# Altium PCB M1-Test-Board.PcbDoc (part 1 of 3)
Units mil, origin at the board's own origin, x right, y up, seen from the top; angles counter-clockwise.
Board outline 3977 x 5000 mil, 4 copper layers (Top, GND Layer 2, Power Layer 3, Bottom), stack 60 mil thick; 191 components, 124 nets, 579 pads, 189 vias.
Unrouted connection lines stored in the file: 80.
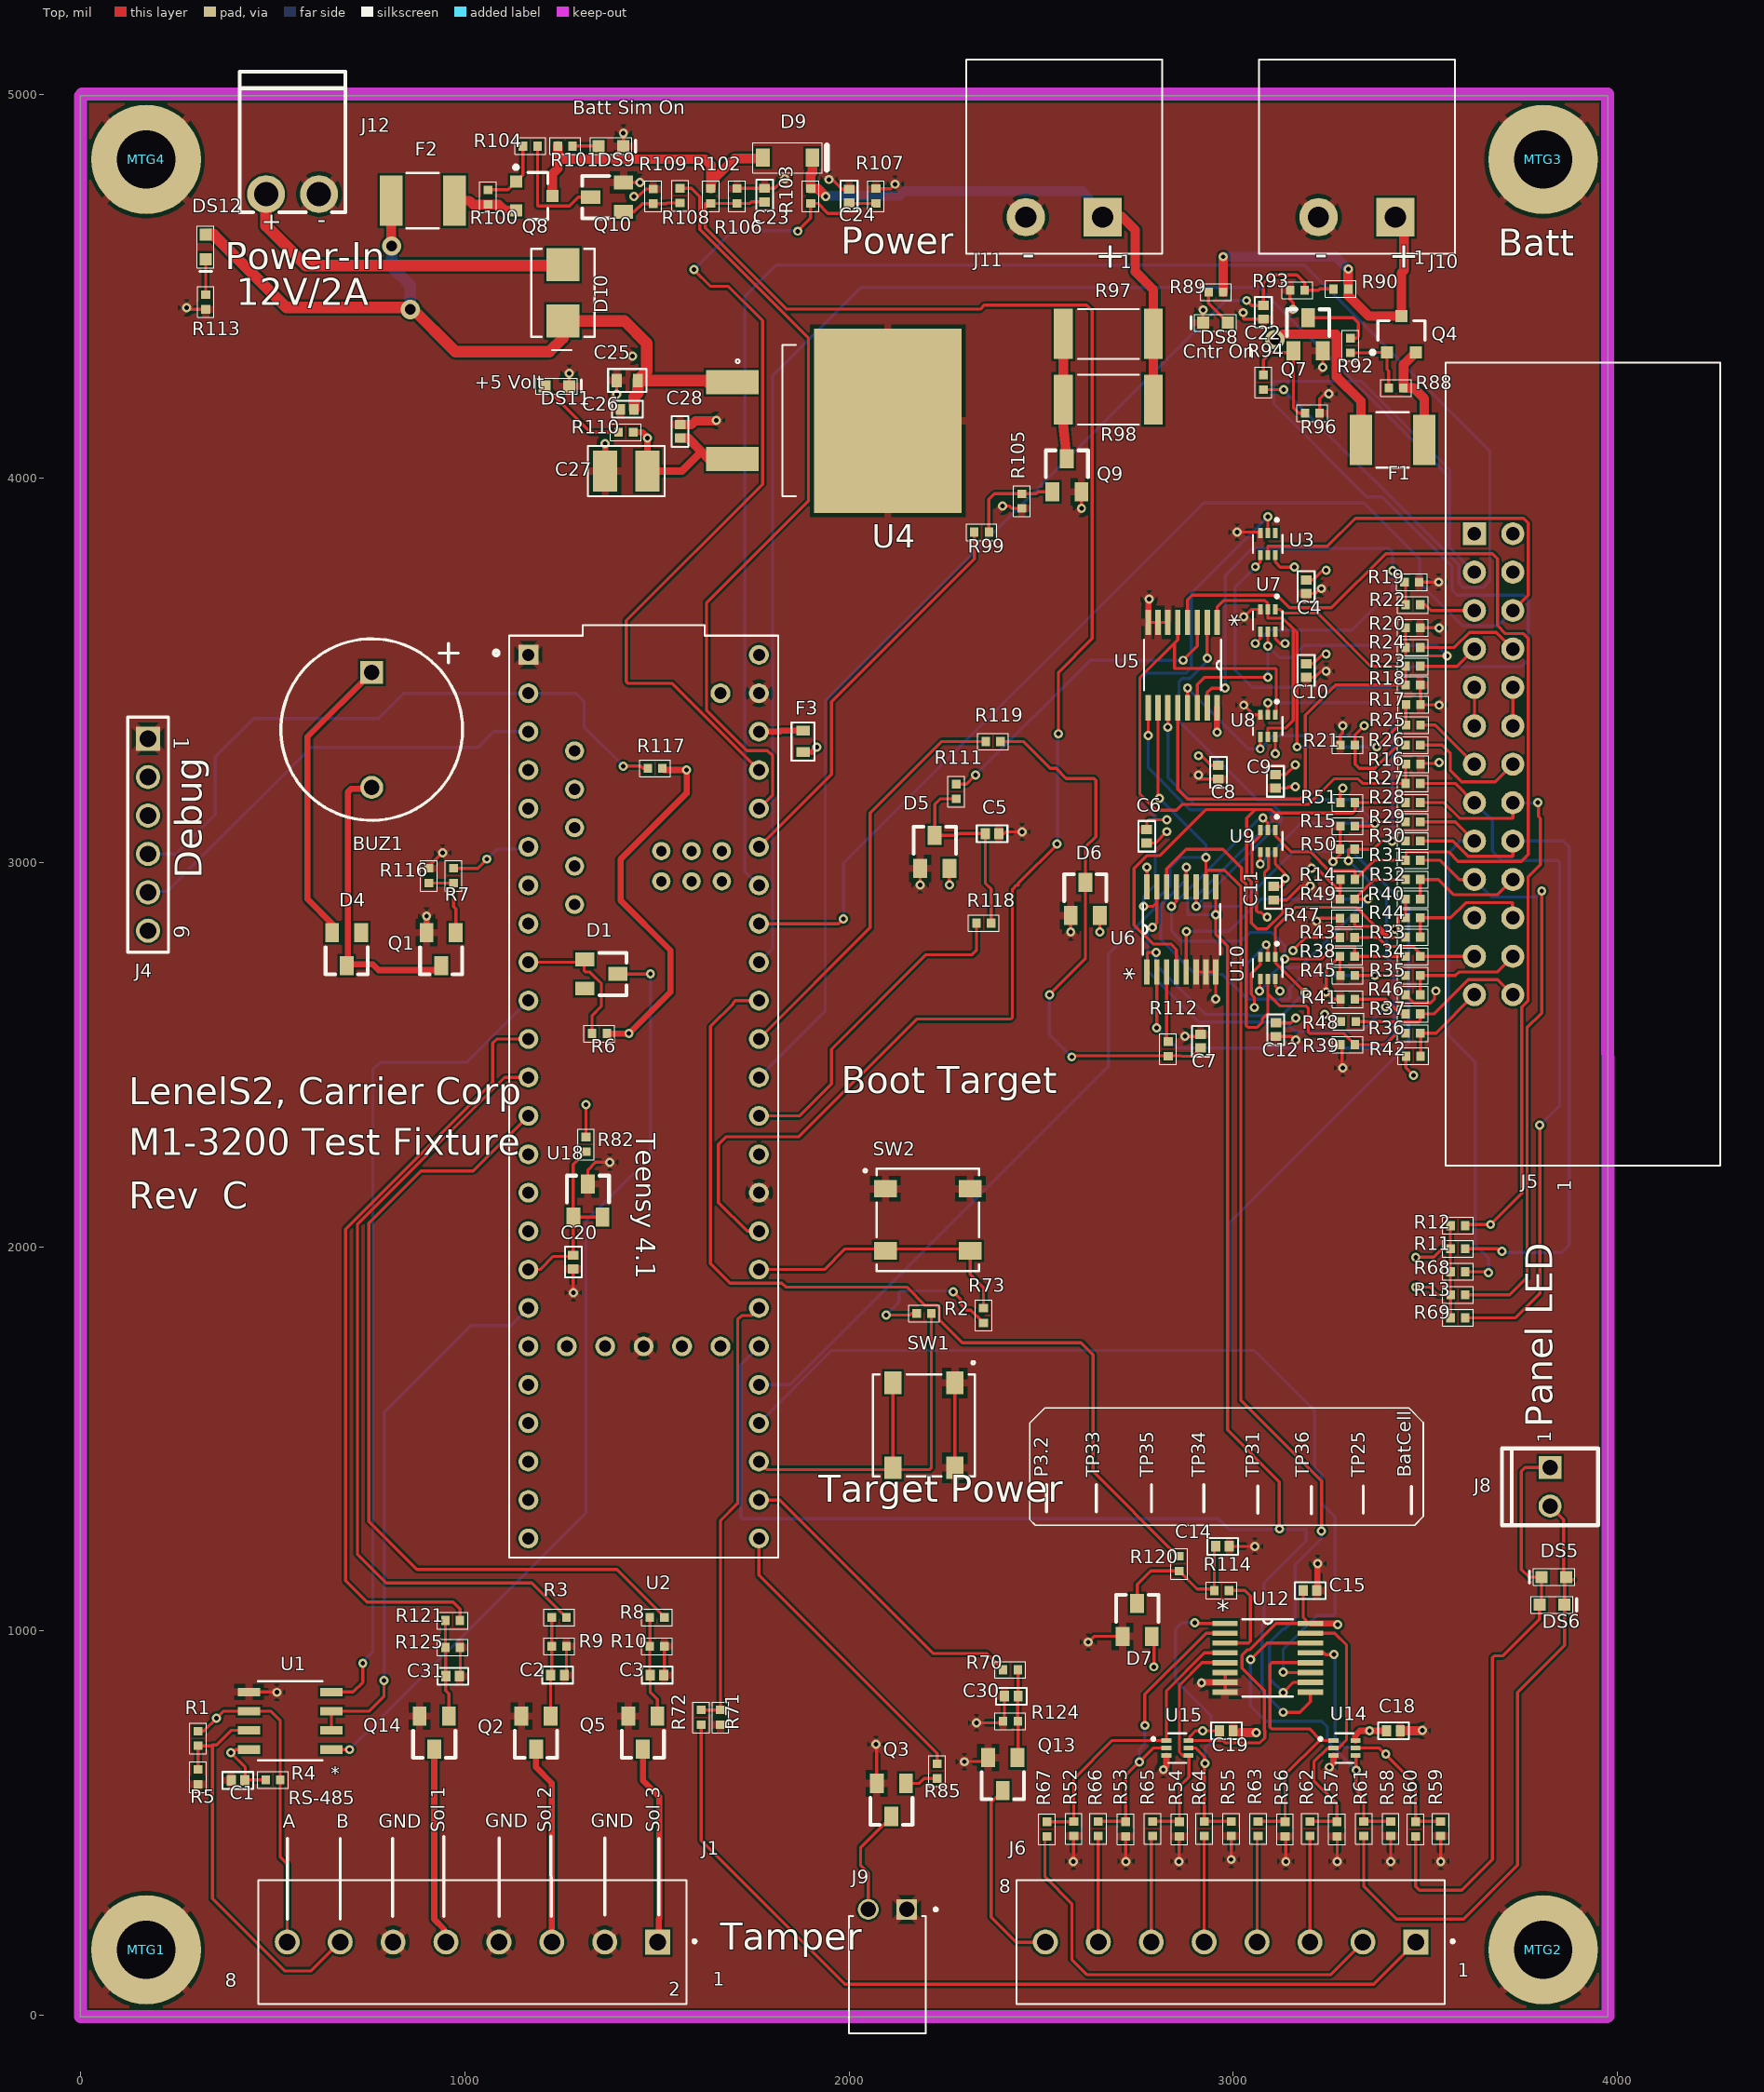
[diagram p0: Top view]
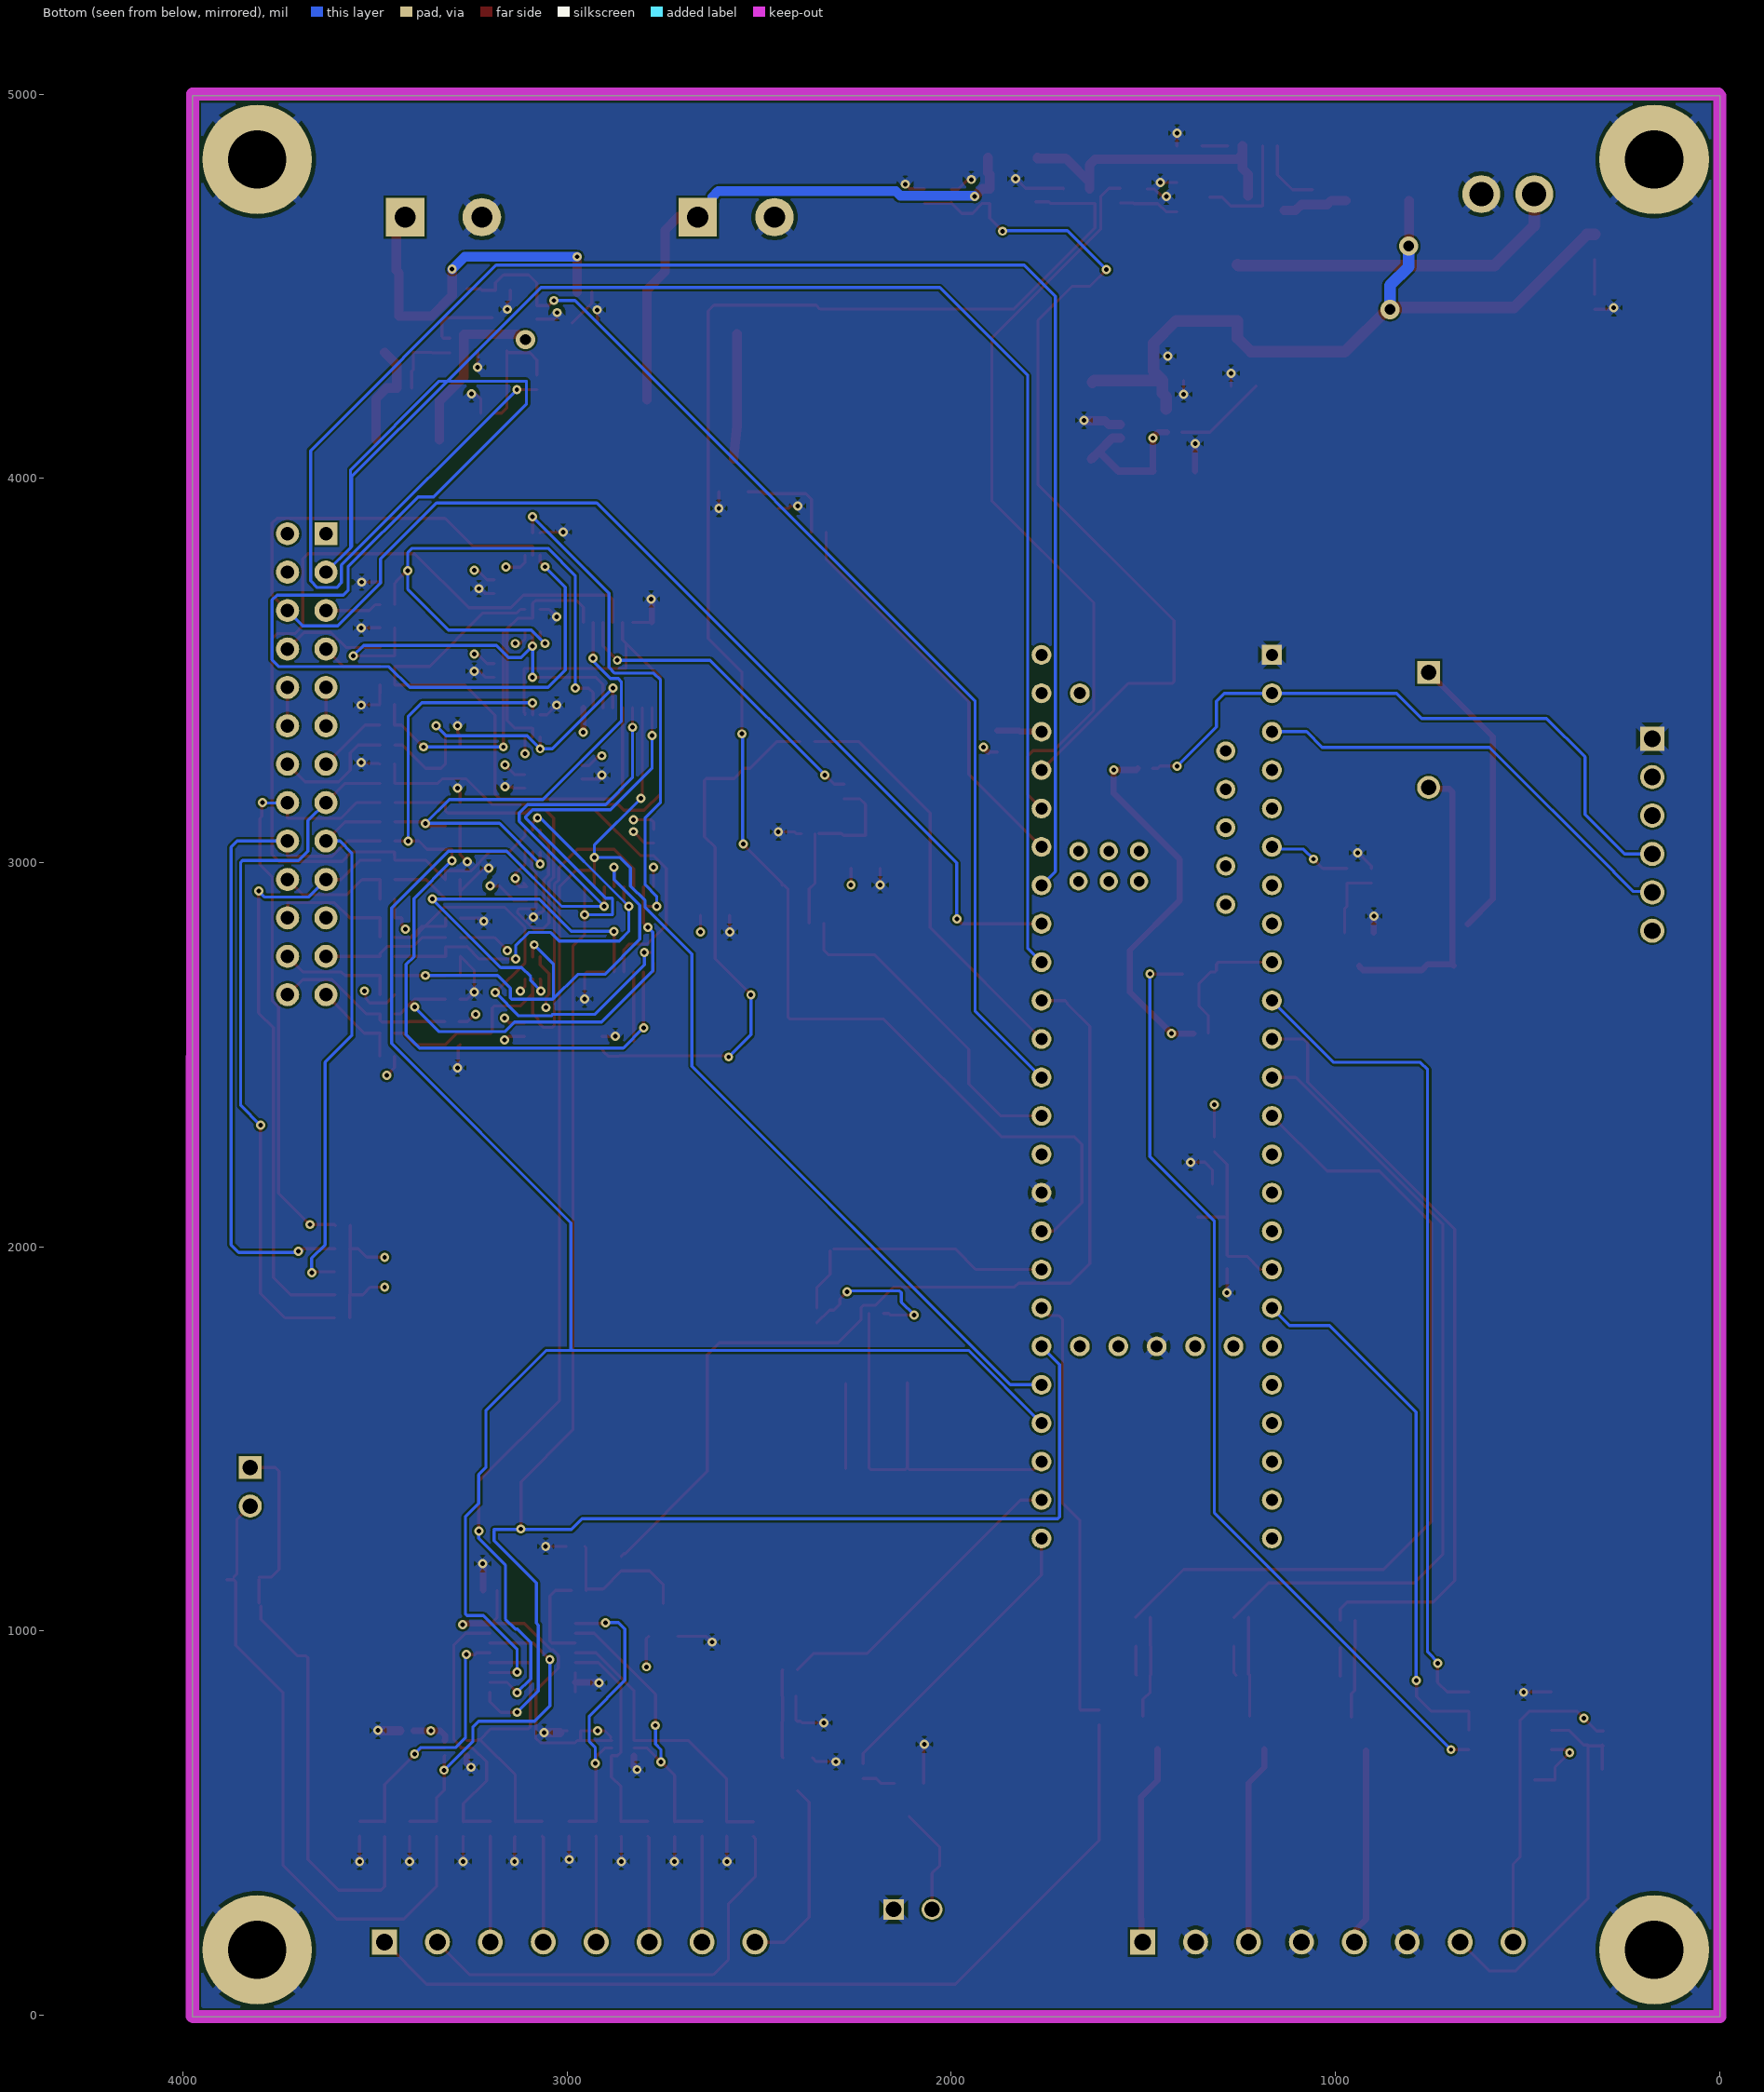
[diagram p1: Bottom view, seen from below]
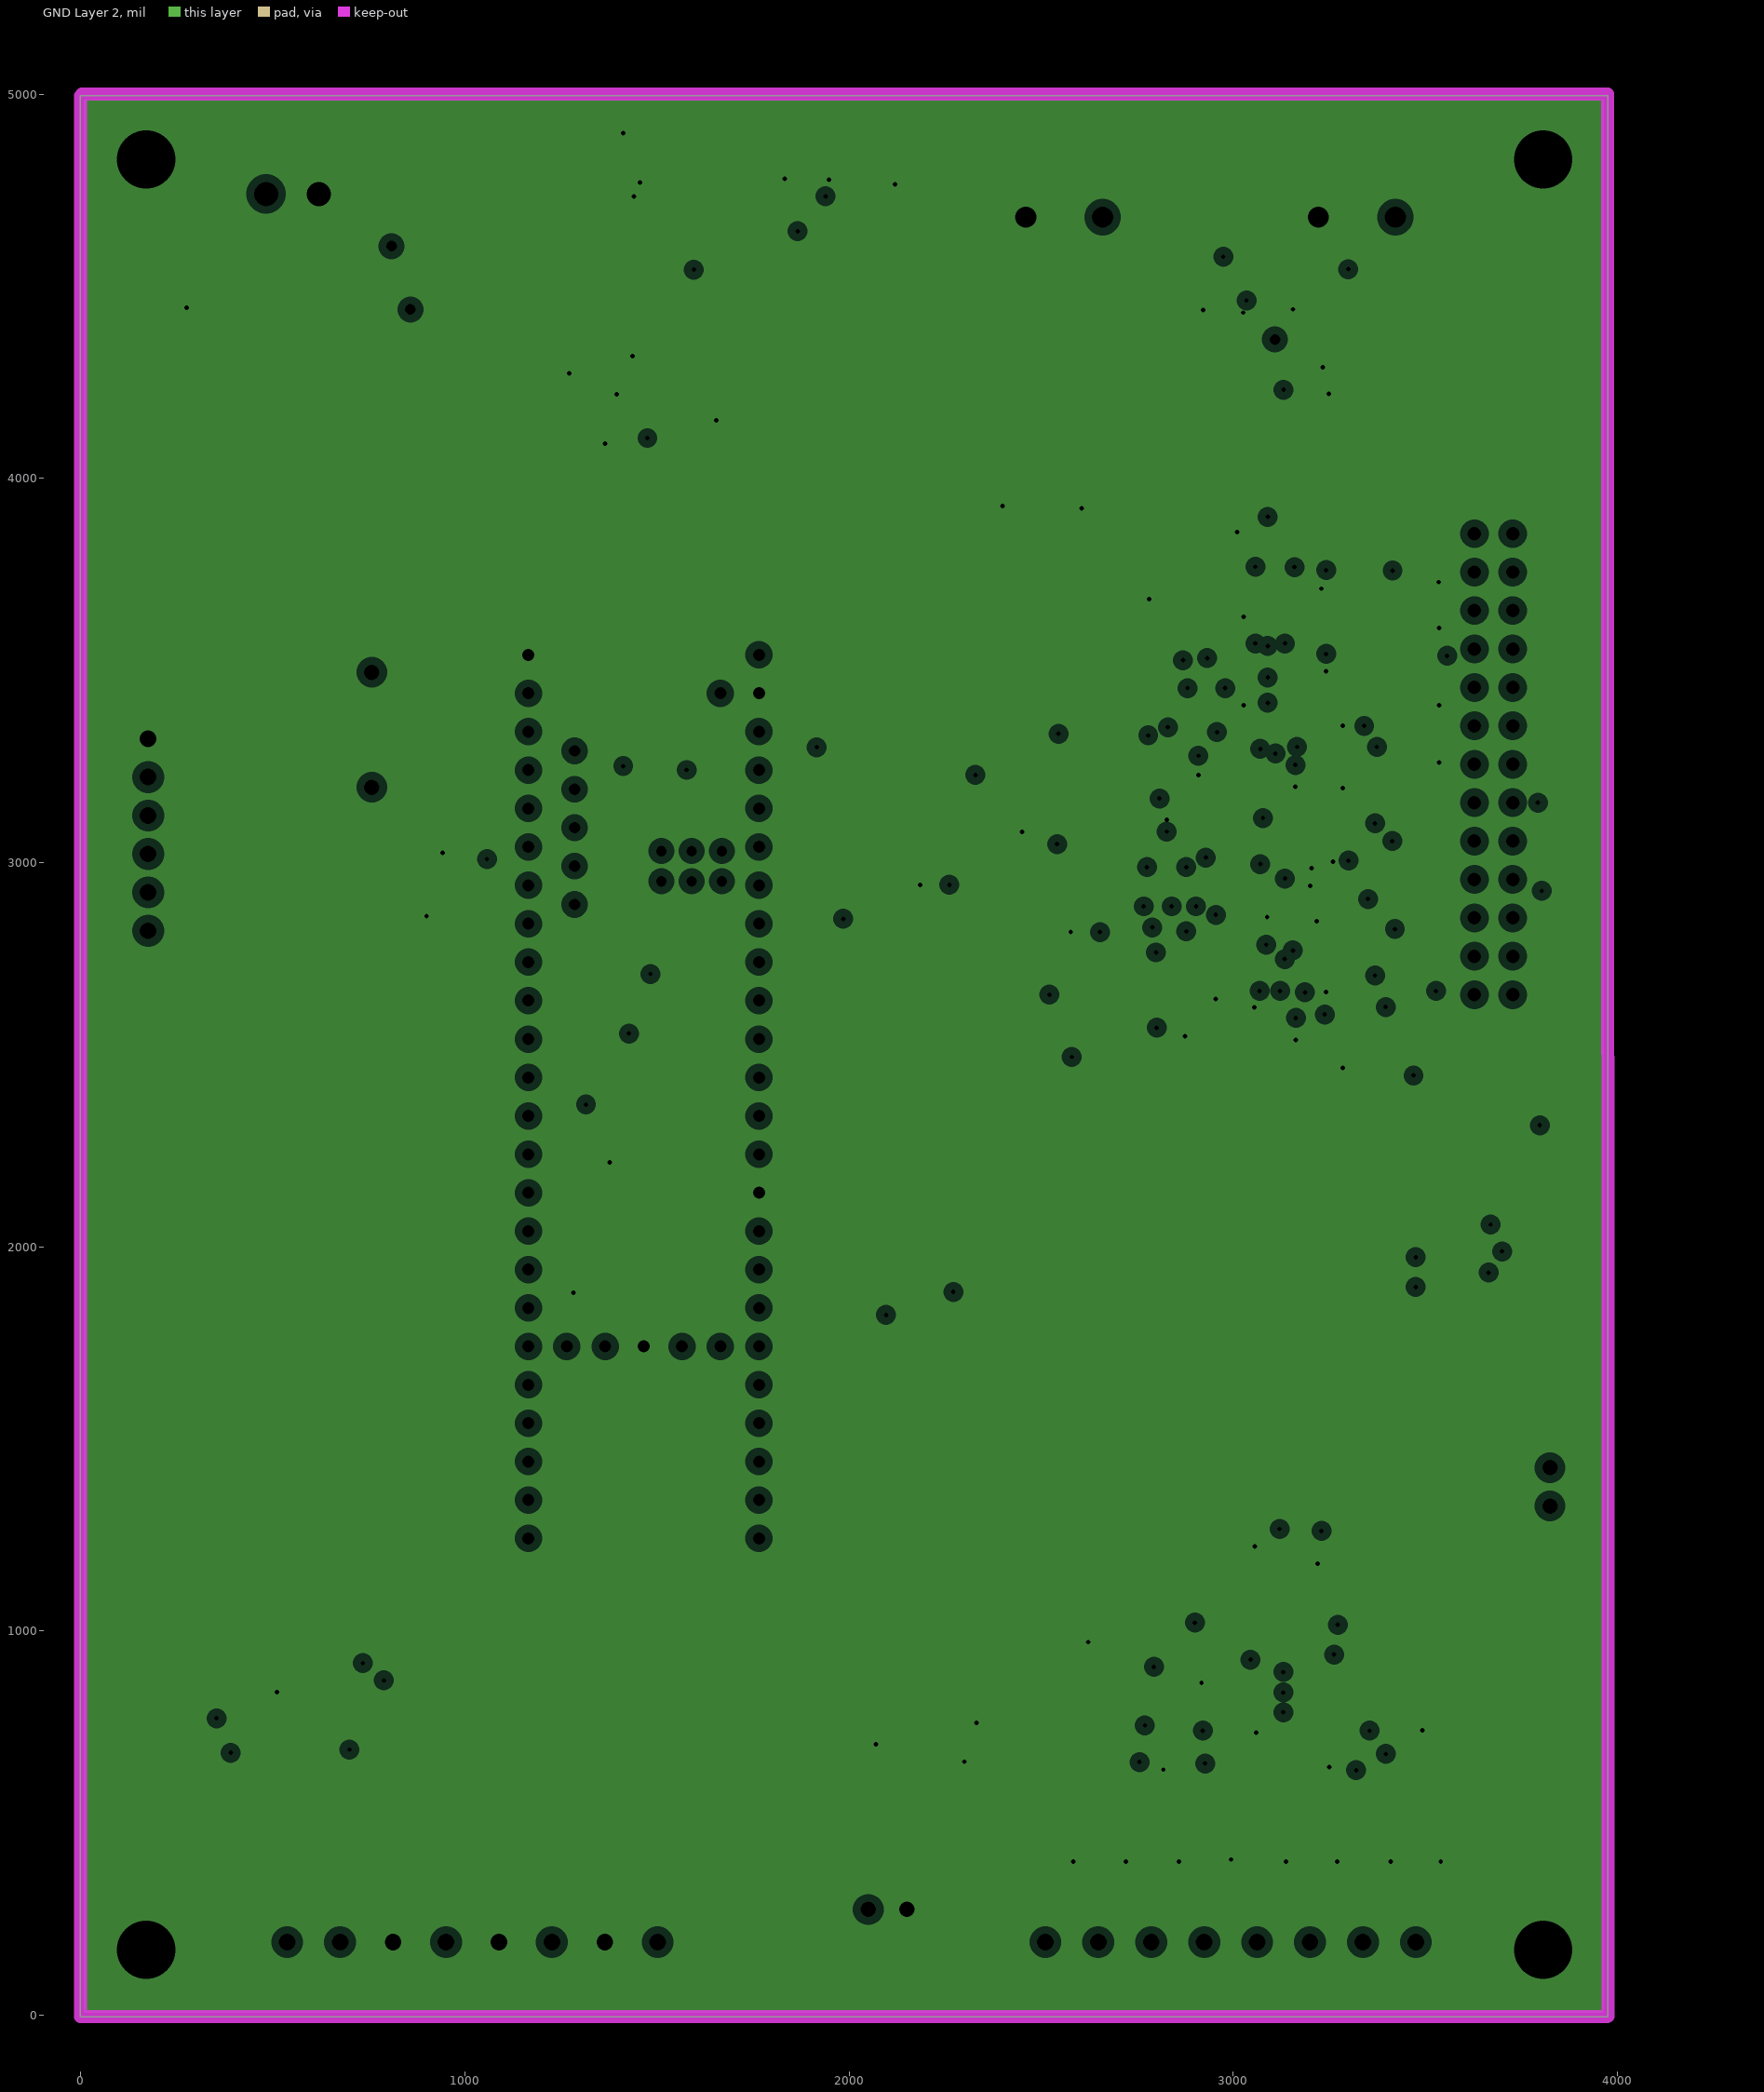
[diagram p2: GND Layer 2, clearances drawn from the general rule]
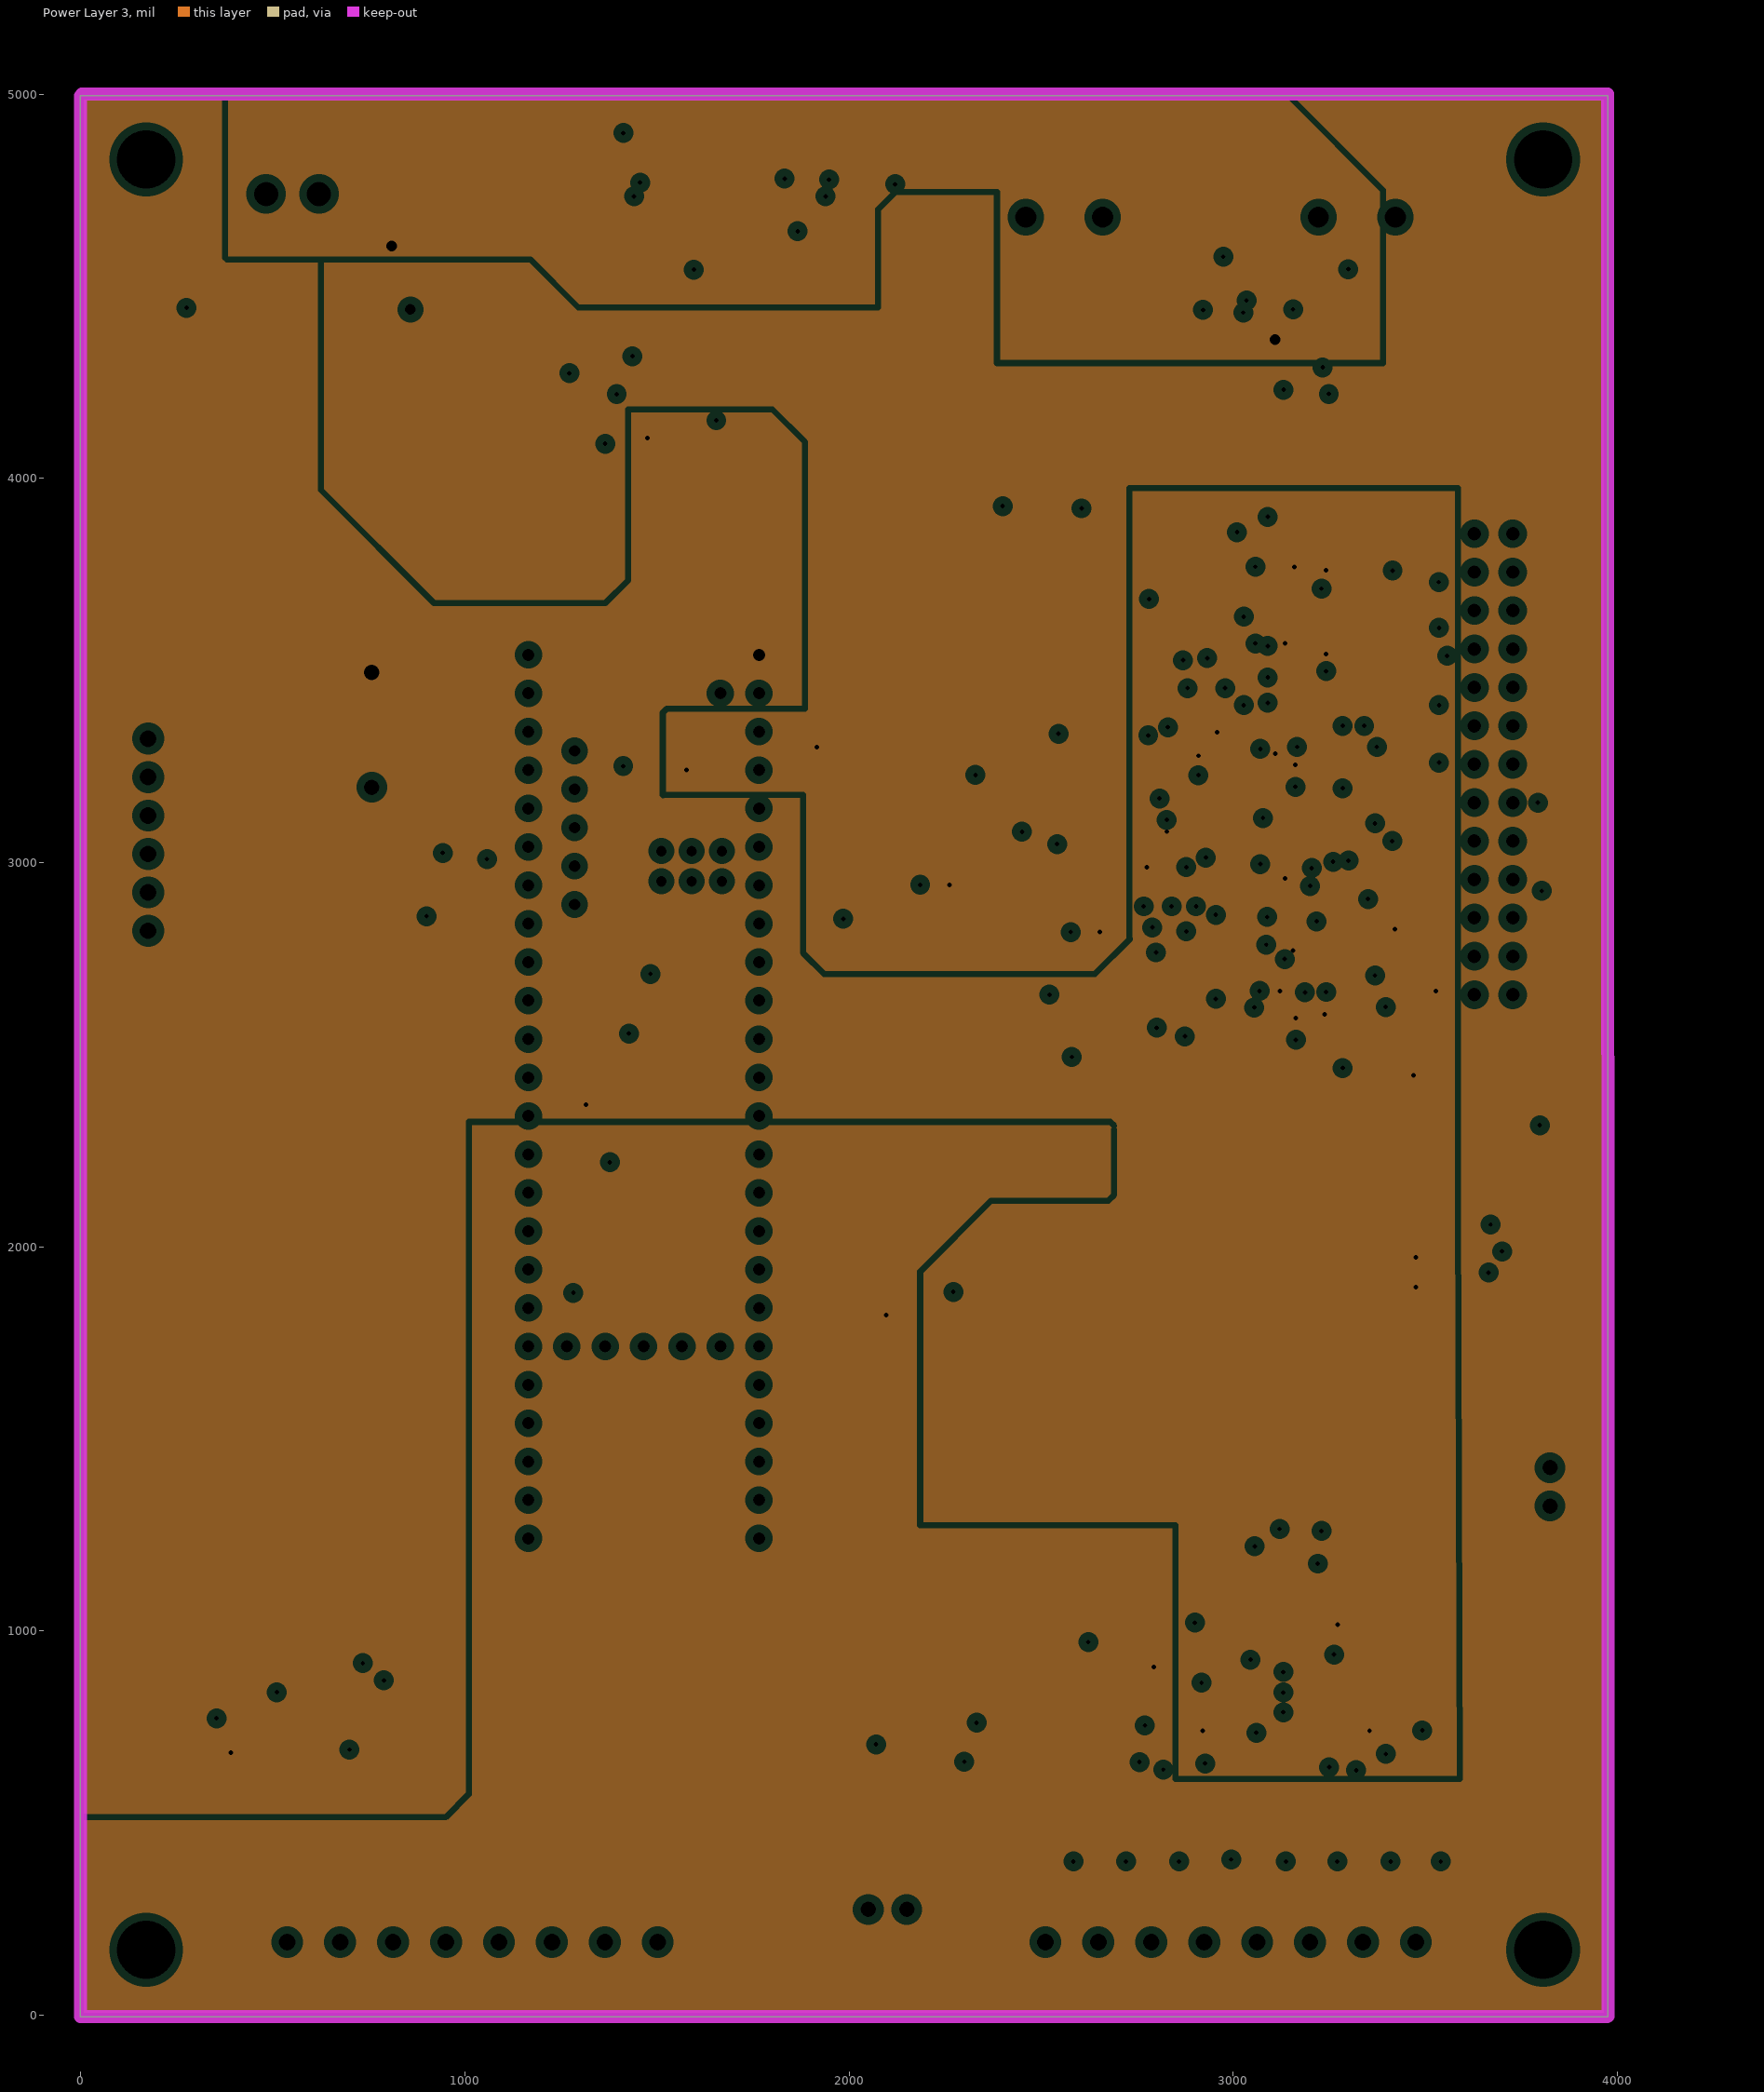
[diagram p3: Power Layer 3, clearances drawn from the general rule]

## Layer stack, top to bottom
Solder Mask Top: solder mask 1, Solder Resist, Dk 3.2
Top: signal copper 0.7
Dielectric 1: prepreg 9.1, 2 x 2116, Dk 4.3
GND Layer 2: plane copper 0.7, net GND
Dielectric2: core 39, Core, Dk 4.6
Power Layer 3: plane copper 0.7, net (Multiple Nets)
Dielectric3: prepreg 9.1, 2 x 2116, Dk 4.3
Bottom: signal copper 0.7
Solder Mask Bottom: solder mask 1, Solder Resist, Dk 3.2

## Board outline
3975,-4 -2,-4 -2,4996 3975,4996

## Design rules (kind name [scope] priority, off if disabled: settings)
BoardOutlineClearance BoardOutlineClearance_1 [InComponent('J5') or InComponent('J10') or InComponent('J11') or  InComponent('J8') or  InComponent('J9') or  InComponent('J1') or  InComponent('J2') or   InComponent('J3') or  InComponent('J12')] p1: gap=0 ignorepadtopadclearanceinfootprint=FALSE
BoardOutlineClearance [All] p2: gap=17 ignorepadtopadclearanceinfootprint=FALSE
Clearance "Clearance NPH" [InNet('NetMTG1_1') or InNet('NetMTG4_1') or InNet('NetMTG2_1') or InNet('NetMTG3_1')] p1: gap=10 ignorepadtopadclearanceinfootprint=FALSE
Clearance "Via in PAd U1" [IsVia and InNet('GND') vs IsSMTPin AND InComponent('U1')] p2: gap=0 ignorepadtopadclearanceinfootprint=TRUE
Clearance "Via in PAd U12" [IsVia and InNet('GND') vs IsSMTPin AND InComponent('U12')] p3: gap=0 ignorepadtopadclearanceinfootprint=TRUE
Clearance "Clearance - NetClass - DIF-PAIRS" [InNetClass('DIF-PAIRS')] p4: gap=6 ignorepadtopadclearanceinfootprint=FALSE
Clearance "Clearance - Default - DEFAULT - Via" [IsVia vs IsVia] p5: gap=6 ignorepadtopadclearanceinfootprint=FALSE
Clearance "Clearance - Default - DEFAULT- SMD" [IsVia vs IsSMTPin] p6: gap=6 ignorepadtopadclearanceinfootprint=TRUE
Clearance "Clearance - Default - DEFAULT - Net_1" [All] p7: gap=5.5 ignorepadtopadclearanceinfootprint=FALSE
ComponentClearance "ComponentClearance - Default - DEFAULT" [All] p1: gap=7 collisioncheckmode=3 verticalgap=10 showdistances=FALSE
DiffPairsRouting DiffPair_100DiffPairsRouting [InDifferentialPairClass('diffpair_100')] p1: maxlimit=6.5 minlimit=6.5 mostfreqgap=6.5 toplayer_minwidth=8 toplayer_maxwidth=8 toplayer_prefwidth=8 bottomlayer_minwidth=8 bottomlayer_maxwidth=8 bottomlayer_prefwidth=8 maxuncoupledlength=500
FanoutControl Fanout_SOIC [IsSOIC] p1: bgadir=Out bgaviamode=Centered fanoutstyle=Auto fanoutdirection=Alternating viagrid=1 // Fanout_SOIC (Default Rule)
FanoutControl Fanout_Small [(CompPinCount < 5)] p2: bgadir=Out bgaviamode=Centered fanoutstyle=Auto fanoutdirection=OutThenIn viagrid=1 // Fanout_Small (Default Rule)
FanoutControl Fanout_LCC [IsLCC] p3: bgadir=Out bgaviamode=Centered fanoutstyle=Auto fanoutdirection=Alternating viagrid=1 // Fanout_LCC (Default Rule)
FanoutControl Fanout_BGA [IsBGA] p4: bgadir=Out bgaviamode=Centered fanoutstyle=Auto fanoutdirection=Alternating viagrid=1 // Fanout_BGA (Default Rule)
HoleSize [All] p1: absolutevalues=TRUE maxlimit=180 minlimit=1 maxpercent=80.000 minpercent=20.000
HoleToHoleClearance "HoleToHoleClearance - Default - DEFAULT" [All] p1: gap=7 allowstackedmicrovias=TRUE
Length "Default Length" [All] p1: maxlimit=50000 minlimit=0
MatchedLengths DiffPair_100MatchedLengths [InDifferentialPairClass('diffpair_100')] p1: tolerance=10 checknetsindiffpair=TRUE checkdiffpairvsdiffpair=FALSE checkxsignals=FALSE checkothers=FALSE
MaxMinImpedance "Default Impedance" [All] p1: minimum=50.00 maximum=150.0
MinimumAnnularRing [All] p1: minimumring=6
MinimumSolderMaskSliver [All] p1: minsoldermaskwidth=1
ParallelSegment "Default Parallel Segment Same Layer" [All] p1: limit=1000 gap=20
ParallelSegment "Default Parallel Segment Adjasent" [All] p2: limit=1000 gap=200
PlaneClearance "PlaneClearance - FootPrint 'RJ45$2F$SI-46001'" [HasFootprint('RJ45$2F$SI-46001')] p1: clearance=15 // PAD - Power Plane Clearance
PlaneConnect "Default PlaneConnect" [All] p1: planeconnectstyle=Relief reliefexpansion=20 reliefentries=4 reliefconductorwidth=20 reliefairgap=10
PolygonConnect "PolygonConnect - Default SMT" [IsSMTPin] p1: connectstyle=Relief reliefconductorwidth=20 reliefentries=4 polygonreliefangle="90 Angle" airgapwidth=10
PolygonConnect "PolygonConnect - Default Pad" [All] p2: connectstyle=Relief reliefconductorwidth=20 reliefentries=4 polygonreliefangle="45 Angle" airgapwidth=10
RoutingLayers "RoutingLayers - Default - DEFAULT" [All] p1: top layer_v5=TRUE bottom layer_v5=TRUE
RoutingPriority "RoutingPriority - Default - DEFAULT" [All] p1: routingpriority=3
RoutingTopology "Default Routing Topology" [All] p1: topology=Shortest
RoutingVias "RoutingVias - Default - DEFAULT" [All] p1: holewidth=12 width=24 viastyle="Through Hole" minholewidth=12 minwidth=24 maxholewidth=20 maxwidth=40
SMDToCorner "SMDToCorner - Default - DEFAULT" [All] p1: distance=20000
SilkToSilkClearance [All] p1: silktosilkclearance=3
SilkToSolderMaskClearance [IsPad] p1: minsilkscreentomaskgap=3 clearancetoexposedcopper=TRUE
SolderMaskExpansion "SolderMaskExpansion from CAM settings" [All] p1: expansion=2 istentingtop=FALSE
Width "Width - NetClass - PWR+GND" [InNetClass('PWR+GND')] p1: maxlimit=250 minlimit=8 preferedwidth=20
Width "Width - NetClass - HI" [InNetClass('HI')] p2: maxlimit=30 minlimit=20 preferedwidth=25
Width "Width - NetClass - DIF-PAIRS" [InNetClass('DIF-PAIRS')] p3: maxlimit=250 minlimit=5 preferedwidth=7
Width "Default Width" [All] p4: maxlimit=250 minlimit=3 preferedwidth=8
14 further rules are at their usual default settings.

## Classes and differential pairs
net class HI: +12V NetD9_1 NetD9_2 NetD10_1 NetF1_2 NetF2_2 NetJ10_1 NetQ9_3
component class RibbonCable: C4 C5 C6 C7 C8 C9 C10 C11 C12 D5 D6 J5 R11 R12 R13 R14 R15 R16 R17 R18 R19 R20 R21 R22 R23 R24 R25 R26 R27 R28 R29 R30 R31 R32 R33 R34 R35 R36 R37 R38 R39 R40 R41 R42 R43 R44 R45 R46 R47 R48 R49 R50 R51 R68 R69 R111 R112 R118 R119 U3 U5 U6 U7 U8 U9 U10
component class InputOutput: C14 C15 C18 C19 D7 DS5 DS6 J6 J8 J9 Q3 R52 R53 R54 R55 R56 R57 R58 R59 R60 R61 R62 R63 R64 R65 R66 R67 R71 R72 R85 R114 R120 U12 U14 U15
component class Teensy: BUZ1 C1 C2 C3 C20 C30 C31 D1 D4 F3 J1 J4 MTG1 MTG2 MTG3 MTG4 Q1 Q2 Q5 Q13 Q14 R1 R2 R3 R4 R5 R6 R7 R8 R9 R10 R70 R73 R82 R116 R117 R121 R124 R125 SW1 SW2 U1 U2 U18
component class Power: C22 C23 C24 C25 C26 C27 C28 D9 D10 DS8 DS9 DS11 DS12 F1 F2 J10 J11 J12 Q4 Q7 Q8 Q9 Q10 R88 R89 R90 R92 R93 R94 R96 R97 R98 R99 R100 R101 R102 R103 R104 R105 R106 R107 R108 R109 R110 R113 U4

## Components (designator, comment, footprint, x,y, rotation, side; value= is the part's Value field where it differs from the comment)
BUZ1 "CEM-1205-IC" BUZZ-MB5120C 757.27,3495 r180 top
C1 "0.1uF" C0402 409,610.71 r180 top
C2 "1uF" C0402 1241,885 r0 top
C3 "1uF" C0402 1500,885 r0 top
C4 "0.1uF" C0402 3190,3718.19 r90 top
C5 "0.1uF" C0402 2372.3,3075 r0 top
C6 "0.1uF" C0402 2775,3068.3 r270 top
C7 "0.1uF" C0402 2915,2535 r90 top
C8 "0.1uF" C0402 2961.57,3235 r90 top
C9 "0.1uF" C0402 3110,3211.3 r90 top
C10 "0.1uF" C0402 3190,3500 r90 top
C11 "0.1uF" C0402 3105,2920 r90 top
C12 "0.1uF" C0402 3111,2565 r90 top
C14 "0.1uF" C0402 2972.3,1220 r0 top
C15 "0.1uF" C0402 3200,1105 r180 top
C18 "0.1uF" C0402 3417.3,740 r180 top locked
C19 "0.1uF" C0402 2982.3,740 r180 top locked
C20 "0.47uF" C0402 1282,1960 r270 top
C22 "1uF" C0402 3078.5,4432.3 r270 top
C23 "1uF" C0402 1780,4737.3 r90 top
C24 "1uF" C0402 2000,4735 r90 top
C25 "4.7uF" C0603 1422.56,4255 r270 top
C26 "0.1uF" C0402 1422.56,4180 r0 top
C27 "47uF" C1210 1420.12,4019 r270 top
C28 "0.1uF" C0402 1560,4122.3 r270 top
C30 "1uF" C0402 2422.3,830 r180 top
C31 "1uF" C0402 968,882 r0 top
D1 "BAT54S" sot23-3 1355,2710 r270 top
D4 "BAT54S" sot23-3 692,2774.42 r180 top
D5 "BAT54S" sot23-3 2223,3028 r0 top
D6 "BAT54S" sot23-3 2615,2905 r0 top locked
D7 "BAT54S" sot23-3 2750,1028.77 r0 top
D9 "B5819W-TP" MCC-SOD123_V 1840,4835 r0 top
D10 "B240Q-13-F" DIODE_DO214AA 1255,4483 r270 top
DS5 "LTST-C193KRKT-5A" LED-RED_0603 3835,1140 r180 top
DS6 "LTST-C193TBKT-5A" LED-BLUE_0603 3830,1067.95 r0 top
DS8 "LTST-C193KSKT-5A" LED-YELLOW_0603 2953.98,4405 r180 top
DS9 "LTST-C193KFKT-5A" LED-ORANGE_0603 1380,4865 r0 top
DS11 "LTST-C193TGKT-5A" LED-GREEN_0603 1239.09,4240 r0 top
DS12 "LTST-C193KRKT-5A" LED-RED_0603 325,4602.48 r270 top
F1 "500mA" FUSE_F050-2 3415,4100 r0 top locked
F2 "500mA" FUSE_F050-2 890,4723.07 r0 top
F3 "50mA" F0603 1880,3315 r0 top locked
J1 "284391-8" TE_284391-8 1019.49,190 r180 top
J4 "61300611121" 61300611121 175,3072.42 r270 top
J5 "N3429-5202RB" CONN_N3429-5202RB 3628,3856 r270 top locked
J6 "284391-8" TE_284391-8 2993.31,190 r180 top
J8 "640454-2" CON$5C$2P$5C$100LM 3825,1425 r270 top
J9 "640457-2" TE_640457-2 2150,275 r180 top
J10 "Green 5.08mm" Conn_5433668 3422,4680 r0 top
J11 "Gray 5.08mm" Conn_5442002 2660,4680 r0 top
J12 "EBSA-02-A" CONN-TH_2P-P3.50_JL15EDGRC-35002G01 551.1,4740 r180 top
MTG1 "152mil" MNT-HOLE-169-350#1 160,160 r0 top
MTG2 "152mil" MNT-HOLE-169-350#2 3800,180 r0 top locked
MTG3 "152mil" MNT-HOLE-169-350#3 3800,4830 r0 top
MTG4 "152mil" MNT-HOLE-169-350#4 170,4810.98 r0 top
Q1 "MMBT3904" sot23-3 938,2774.42 r180 top
Q2 "MMBT3904" sot23-3 1185,735 r180 top
Q3 "MMBT3904" sot23-3 2110,560 r180 top
Q4 "AO3401A" AO-SOT-23-3L_V 3437.88,4375 r90 top
Q5 "MMBT3904" sot23-3 1463,735 r180 top
Q7 "MMBT3904" sot23-3 3195,4375 r0 top
Q8 "AO3401A" AO-SOT-23-3L_V 1180,4735 r0 top
Q9 "MMBT3904" sot23-3 2567,4008 r0 top locked
Q10 "MMBT3904" sot23-3 1370,4732.13 r90 top
Q13 "MMBT3904" sot23-3 2400,626.93 r180 top
Q14 "MMBT3904" sot23-3 920,735 r180 top
R1 "120R" R0402 305,720 r90 top
R2 "10K 1%" R0402 2195,1826.16 r180 top
R3 "10K 1%" R0402 1245,1035 r180 top
R4 "330R 1%" R0402 500,612.21 r180 top
R5 "330R 1%" R0402 305,620 r270 top
R6 "5.1K 1%" R0402 1350,2555 r0 top
R7 "1K 1%" R0402 970,2965.87 r270 top
R8 "10K 1%" R0402 1500,1035 r180 top
R9 "100K 1%" R0402 1245,960 r0 top
R10 "100K 1%" R0402 1500,960 r0 top
R11 "51K 1%" R0402 3585,1995 r180 top
R12 "51K 1%" R0402 3585,2055 r180 top
R13 "51K 1%" R0402 3585.09,1875 r0 top
R14 "51K 1%" R0402 3298,2956 r0 top
R15 "51K 1%" R0402 3298,3095 r0 top
R16 "51K 1%" R0402 3468.91,3256 r180 top
R17 "2.8K 1%" R0402 3468.91,3411 r180 top
R18 "8.2K 1%" R0402 3468,3462.02 r180 top
R19 "8.2K 1%" R0402 3465,3730 r180 top
R20 "8.2K 1%" R0402 3468,3611 r180 top
R21 "2.8K 1%" R0402 3298,3306 r0 top
R22 "10K 1%" R0402 3468,3671 r0 top
R23 "10K 1%" R0402 3468,3511 r0 top
R24 "10K 1%" R0402 3468,3559.79 r180 top
R25 "10K 1%" R0402 3468.91,3357.95 r0 top
R26 "10K 1%" R0402 3468,3306 r180 top
R27 "10K 1%" R0402 3468,3206 r0 top
R28 "10K 1%" R0402 3468,3156 r180 top
R29 "10K 1%" R0402 3468,3106 r0 top
R30 "10K 1%" R0402 3468,3056 r180 top
R31 "10K 1%" R0402 3468,3005.88 r0 top
R32 "10K 1%" R0402 3468,2956 r180 top
R33 "10K 1%" R0402 3468,2806 r180 top
R34 "10K 1%" R0402 3468,2756 r0 top
R35 "10K 1%" R0402 3468,2706 r180 top
R36 "10K 1%" R0402 3468,2556 r0 top
R37 "10K 1%" R0402 3468,2606 r180 top
R38 "10K 1%" R0402 3297.09,2756 r180 top
R39 "10K 1%" R0402 3298,2526 r180 top
R40 "10K 1%" R0402 3468,2904.98 r0 top
R41 "10K 1%" R0402 3298,2644.19 r0 top
R42 "10K 1%" R0402 3468.91,2496 r180 top
R43 "10K 1%" R0402 3297.09,2805 r180 top
R44 "10K 1%" R0402 3468,2856 r0 top
R45 "10K 1%" R0402 3298,2706 r0 top
R46 "10K 1%" R0402 3468,2656 r0 top
R47 "10K 1%" R0402 3297.09,2855 r0 top
R48 "10K 1%" R0402 3299.93,2586 r0 top
R49 "10K 1%" R0402 3297.09,2904.98 r0 top
R50 "51K 1%" R0402 3297.09,3034.79 r0 top
R51 "51K 1%" R0402 3298,3156 r0 top
R52 "10K 1%" R0402 2585,485 r90 top locked
R53 "51K 1%" R0402 2720,484.09 r90 top locked
R54 "51K 1%" R0402 2860,484.09 r90 top locked
R55 "51K 1%" R0402 2995,485 r90 top locked
R56 "51K 1%" R0402 3135,484.09 r90 top locked
R57 "51K 1%" R0402 3270,484.09 r90 top locked
R58 "2.8K 1%" R0402 3410,485 r90 top locked
R59 "2.8K 1%" R0402 3540,485 r90 top
R60 "10K 1%" R0402 3475,484.09 r270 top
R61 "10K 1%" R0402 3340,485 r270 top locked
R62 "10K 1%" R0402 3200,485 r270 top locked
R63 "10K 1%" R0402 3065,485 r270 top locked
R64 "10K 1%" R0402 2925,485 r270 top locked
R65 "10K 1%" R0402 2790,485 r270 top locked
R66 "10K 1%" R0402 2648.82,485 r270 top locked
R67 "10K 1%" R0402 2515,484.09 r270 top locked
R68 "51K 1%" R0402 3585,1935 r0 top
R69 "51K 1%" R0402 3585,1815 r0 top
R70 "10K 1%" R0402 2420,898.61 r0 top
R71 "51K 1%" R0402 1665.2,775 r90 top
R72 "51K 1%" R0402 1615,775 r270 top
R73 "10K 1%" R0402 2350,1820.99 r270 top
R82 "330R 1%" R0402 1315,2266.38 r270 top
R85 "1K 1%" R0402 2229.03,635 r270 top locked
R88 "10K 1%" R0402 3424.09,4235 r180 top locked
R89 "5.1K 1%" R0402 2955,4485 r0 top
R90 "10K 1%" R0402 3280.36,4493 r0 top
R92 "10K 1%" R0402 3305,4345.91 r90 top
R93 "2.8K 1%" R0402 3167.21,4490 r180 top
R94 "10K 1%" R0402 3078.5,4250 r90 top locked
R96 "100K 1%" R0402 3205.91,4170 r0 top locked
R97 "220R 5%" RESC6331X75N 2675,4376.02 r180 top
R98 "220R 5%" RESC6331X75N 2675,4205 r180 top locked
R99 "10K 1%" R0402 2345,3860 r0 top locked
R100 "10K 1%" R0402 1060,4732.13 r90 top
R101 "5.1K 1%" R0402 1260.91,4865 r180 top
R102 "10K 1%" R0402 1640,4735 r90 top
R103 "10K 1%" R0402 1900,4735 r90 top
R104 "10K 1%" R0402 1170,4865 r0 top
R105 "100K 1%" R0402 2450,3940.91 r270 top locked
R106 "2.8K 1%" R0402 1708,4735 r90 top
R107 "2.8K 1%" R0402 2070,4735 r90 top
R108 "10K 1%" R0402 1560,4735.91 r270 top
R109 "100K 1%" R0402 1490,4734.09 r90 top
R110 "680R 1%" R0402 1418.91,4120 r180 top
R111 "2.8K 1%" R0402 2279,3185 r90 top locked
R112 "2.8K 1%" R0402 2830.73,2515 r90 top
R113 "5.1K 1%" R0402 325,4459.09 r270 top
R114 "2.8K 1%" R0402 2970,1105 r0 top
R116 "100K 1%" R0402 905.91,2965.86 r90 top
R117 "10K 1%" R0402 1495,3245 r0 top
R118 "10K 1%" R0402 2350.7,2842.52 r0 top
R119 "10K 1%" R0402 2375,3315 r0 top
R120 "10K 1%" R0402 2859.1,1175 r270 top
R121 "10K 1%" R0402 968,1027 r180 top
R124 "100K 1%" R0402 2420,765 r180 top
R125 "100K 1%" R0402 968,957 r0 top
SW1 "KSC441J70SHLFS" SON4_KSC741JLFS_CNK-red 2195,1535 r270 top
SW2 "KSC741J LFS" SON4_KSC741JLFS_CNK-blue 2205,2070 r0 top
U1 "SP485EEN-L/TR-ND" NSOIC-8 545,766 r180 top
U2 "Teensy 4.1" "MODULE_DEV-16771 - headers" 1465.2,2390.63 r270 top locked
U3 "TPD4E001DRLR" SOTFL50P160X60-6N 3090,3828.94 r270 top
U4 "L7805CD2T-TR" VREG_L7805ACD2T 1960,4150 r0 top
U5 "CD74HC4051PWR" 16-TSSOP-4.4MM 2868.39,3514 r270 top
U6 "CD74HC4051PWR" 16-TSSOP-4.4MM 2865,2826 r90 top
U7 "TPD4E001DRLR" SOTFL50P160X60-6N 3090,3630 r270 top
U8 "TPD4E001DRLR" SOTFL50P160X60-6N 3090,3356 r270 top
U9 "TPD4E001DRLR" SOTFL50P160X60-6N 3090,3056 r270 top
U10 "TPD4E001DRLR" SOTFL50P160X60-6N 3090,2725.79 r270 top
U12 "CD74HC4051PWR" 16-TSSOP-4.4MM 3090,930 r0 top locked
U14 "TPD4E001DRLR" SOTFL50P160X60-6N 3290,695 r0 top locked
U15 "TPD4E001DRLR" SOTFL50P160X60-6N 2855,695 r0 top locked
U18 "NCP431AVSNT1G" sot23-3 1320,2120 r0 top

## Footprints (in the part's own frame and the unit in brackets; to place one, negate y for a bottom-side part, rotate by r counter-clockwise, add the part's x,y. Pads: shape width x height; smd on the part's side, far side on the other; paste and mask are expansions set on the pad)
16-TSSOP-4.4MM [mil]
  rect 66x14 smd: 1(-111,89.57) 2(-111,63.98) 3(-111,38.39) 4(-111,12.8) 5(-111,-12.8) 6(-111,-38.39) 7(-111,-63.98) 8(-111,-89.57) 9(111,-89.57) 10(111,-63.98) 11(111,-38.39) 12(111,-12.8) 13(111,12.8) 14(111,38.39) 15(111,63.98) 16(111,89.57)
  silkscreen extent -66,-101 66,101, body extent -130,-101 130,101, height 47
61300611121 [mm] "Pin Header, pitch 2.54 mm, THT, Vertical, single row, 6p"
  rect 1.6x1.6 hole 1.1: 1(-6.35,0)
  round 1.6 hole 1.1: 2(-3.81,0) 3(-1.27,0) 4(1.27,0) 5(3.81,0) 6(6.35,0)
  silkscreen extent -7.77,-1.35 7.77,1.35, body extent -7.62,-1.27 7.62,1.27, height 8.57
AO-SOT-23-3L_V [mm] "SOT23, 3-Leads, Body 3.1x1.8mm, Pitch 0.95mm"
  rect 0.8x0.8 smd: 1(-1.2,0.95) 2(-1.2,-0.95) 3(1.2,0)
  silkscreen extent -1.32,-1.55 0.9,2.02, body extent -1.5,-1.58 1.5,1.52, height 1.25
BUZZ-MB5120C [mil]
  rect 60x60 / inner round 60 / far side rect 60x60 hole 40: 1(0,0)
  round 60 hole 40: 2(0,299.21)
  silkscreen extent -236,-87 236,385, body extent -234,-86 238,386, height 355
C0402 [mil]
  rect 24x28 smd: 1(-17.7,0) 2(17.7,0)
  silkscreen extent -40,-22 40,22, body extent -21,-11 21,11, height 22
C0603 [mm]
  rect 0.9x0.65 smd: 1(0,0.71) 2(0,-0.7)
  silkscreen extent -0.76,-1.27 0.76,1.27, body extent -0.48,-0.87 0.48,0.87, height 0.87
C1210 [mm]
  rect 2.7x1.6 smd: 1(0,1.397) 2(0,-1.397)
  silkscreen extent -1.65,-2.54 1.65,2.54, body extent -0.9,-1.7 0.9,1.7, height 0.94
CON$5C$2P$5C$100LM [mil]
  rect 60x60 hole 40: 1(0,0)
  round 60 hole 40: 2(100,0)
  silkscreen extent -50,-125 150,125, body extent -53,-123 147,108, height 370
CONN-TH_2P-P3.50_JL15EDGRC-35002G01 [mm]
  round 2.5 hole 1.6: 1(-1.75,0) 2(1.75,0)
  silkscreen extent -3.5,-8.1 3.5,1.2, body extent -3.92,-8.03 3.68,1.17, height 6.91
Conn_5433668 [mil]
  rect 100x100 hole 55 mask+3: 1(0,0)
  round 100 hole 55 mask+3: 2(-200,0)
  silkscreen extent -355,-95 155,410, body extent -339,-79 139,394, height 339
Conn_5442002 [mil]
  rect 100x100 hole 55 mask+3: 1(0,0)
  round 100 hole 55 mask+3: 2(-200,0)
  silkscreen extent -355,-95 155,410, body extent -339,-79 139,394, height 339
CONN_N3429-5202RB [mil]
  rect 60x60 hole 35.04: 1(0,0)
  round 60 hole 35.04: 2(0,100) 3(100,0) 4(100,100) 5(200,0) 6(200,100) 7(300,0) 8(300,100) 9(400,0) 10(400,100) 11(500,0) 12(500,100) 13(600,0) 14(600,100) 15(700,0) 16(700,100) 17(800,0) 18(800,100) 19(900,0) 20(900,100) 21(1000,0) 22(1000,100) 23(1100,0) 24(1100,100) 25(1200,0) 26(1200,100)
  silkscreen extent -445,-75 1645,640, body extent -435,-52 1625,1003, height 366
DIODE_DO214AA [mil]
  rect 86x86 smd: 1(-73,0) 2(73,0)
  silkscreen extent -115,-83 149,83, body extent -110,-77 110,77, height 98
F0603 [mm]
  rect 0.9x0.65 smd: 1(0,0.71) 2(0,-0.7)
  silkscreen extent -0.76,-1.27 0.76,1.27, body extent -0.44,-0.85 0.44,0.85, height 0.56
FUSE_F050-2 [mil]
  rect 59x130 smd paste+0 mask+0: 1(-82.5,0) 2(82.5,0)
  silkscreen extent -42,-72 42,72, body extent -93,-67 93,67, height 33
LED-BLUE_0603 [mm] "SMD, 2-Leads, Body 1.6x0.8mm"
  rect 0.8x0.8 smd: 1(-0.825,0) 2(0.825,0)
  silkscreen extent -1.37,-0.56 1.62,0.56, body extent -0.8,-0.4 0.8,0.4, height 0.4
LED-GREEN_0603 [mm] "SMD, 2-Leads, Body 1.6x0.8mm"
  rect 0.8x0.8 smd: 1(-0.825,0) 2(0.825,0)
  silkscreen extent -1.37,-0.53 1.62,0.53, body extent -0.8,-0.4 0.8,0.4, height 0.4
LED-ORANGE_0603 [mm] "SMD, 2-Leads, Body 1.6x0.8mm"
  rect 0.8x0.8 smd: 1(-0.825,0) 2(0.825,0)
  silkscreen extent -1.37,-0.56 1.62,0.56, body extent -0.8,-0.4 0.8,0.4, height 0.4
LED-RED_0603 [mm] "SMD, 2-Leads, Body 1.6x0.8mm"
  rect 0.8x0.8 smd: 1(-0.825,0) 2(0.825,0)
  silkscreen extent -1.37,-0.56 1.62,0.53, body extent -0.8,-0.4 0.8,0.4, height 0.4
LED-YELLOW_0603 [mm] "SMD, 2-Leads, Body 1.6x0.8mm"
  rect 0.8x0.8 smd: 1(-0.825,0) 2(0.825,0)
  silkscreen extent -1.4,-0.56 1.62,0.56, body extent -0.8,-0.4 0.8,0.4, height 0.4
MCC-SOD123_V [mil] "SOD123, 2-Leads, Body 2.7x1.6mm, Height 1.35mm"
  rect 35.98x47.99 smd: 1(-64.5,0) 2(64.5,0)
  silkscreen extent -90,-39 102,39, body extent -53,-30 53,32, height 53
MNT-HOLE-169-350#1 [mil]
  round 285 / inner round 200 / far side round 285 hole 152: 1(10,10)
MNT-HOLE-169-350#2 [mil]
  round 285 / inner round 200 / far side round 285 hole 152: 1(7,-10)
MNT-HOLE-169-350#3 [mil]
  round 285 / inner round 200 / far side round 285 hole 152: 1(7,0)
MNT-HOLE-169-350#4 [mil]
  round 285 / inner round 200 / far side round 285 hole 152: 1(0,19.02)
"MODULE_DEV-16771 - headers" [mm]
  round 1.308 hole 0.8: 0(-26.67,-7.62) 1(-24.13,-7.62) 2(-21.59,-7.62) 3(-19.05,-7.62) 3.3V_1(6.35,-7.62) 3.3V_2(-24.13,7.62) 3.3V_3(16.51,-2.54) 4(-16.51,-7.62) 5(-13.97,-7.62) 6(-11.43,-7.62) 7(-8.89,-7.62) 8(-6.35,-7.62) 9(-3.81,-7.62) 10(-1.27,-7.62) 11(1.27,-7.62) 12(3.81,-7.62) 13(3.81,7.62) 14(1.27,7.62) 15(-1.27,7.62) 16(-3.81,7.62) 17(-6.35,7.62) 18(-8.89,7.62) 19(-11.43,7.62) 20(-13.97,7.62) 21(-16.51,7.62) 22(-19.05,7.62) 23(-21.59,7.62) 24(8.89,-7.62) 25(11.43,-7.62) 26(13.97,-7.62) 27(16.51,-7.62) 28(19.05,-7.62) 29(21.59,-7.62) 30(24.13,-7.62) 31(26.67,-7.62) 32(29.21,-7.62) 33(29.21,7.62) 34(26.67,7.62) 35(24.13,7.62) 36(21.59,7.62) 37(19.05,7.62) 38(16.51,7.62) 39(13.97,7.62) 40(11.43,7.62) 41(8.89,7.62) GND2(6.35,7.62) GND3(-26.67,7.62) GND4(16.51,0) ON/OFF(16.51,5.08) PROGRAM(16.51,2.54) VBAT(16.51,-5.08) VIN(-29.21,7.62) VUSB(-26.67,5.08)
  round 1.258 hole 0.75: 5V(-22.86,-4.57) D+(-17.78,-4.57) D-(-20.32,-4.57) USB_GND1(-15.24,-4.57) USB_GND2(-12.7,-4.57)
  rect 1.308x1.308 hole 0.8: GND1(-29.21,-7.62)
  round 1.208 hole 0.7: GND5(-14.24,3.17) LED(-16.24,3.17) R+(-16.24,5.17) R-(-14.24,5.17) T+(-14.24,1.17) T-(-16.24,1.17)
  silkscreen extent -31.18,-9.91 30.48,8.89, body extent -30.66,-9.4 30.35,9.27, height 8.14
NSOIC-8 [mil]
  rect 57.5x22 smd paste+0 mask+0: 1(-107.25,75) 2(-107.25,25) 3(-107.25,-25) 4(-107.25,-75) 5(107.25,-75) 6(107.25,-25) 7(107.25,25) 8(107.25,75)
  silkscreen extent -84,-104 84,104, body extent -122,-99 122,99, height 69
R0402 [mm] "Generic R0402 Resistor"
  rect 0.56x0.6 smd: 1(-0.485,0) 2(0.485,0)
  silkscreen extent -1.01,-0.55 1.01,0.55, body extent -0.52,-0.28 0.52,0.28, height 0.41
RESC6331X75N [mm]
  rect 1.26x3.32 smd: 1(-2.975,0) 2(2.975,0)
  silkscreen extent -2.02,-1.65 2.02,1.65, body extent -3.25,-1.73 3.25,1.73, height 0.71
SON4_KSC741JLFS_CNK-blue [mil]
  rect 59x45 smd paste+0 mask+0: 1(-110.5,80.71) 2(110.5,80.71) 3(110.5,-80.71) 4(-110.5,-80.71)
  silkscreen extent -167,-133 133,133, body extent -118,-123 126,123, height 166
SON4_KSC741JLFS_CNK-red [mil]
  rect 59x45 smd paste+0 mask+0: 1(-110.5,80.71) 2(110.5,80.71) 3(110.5,-80.71) 4(-110.5,-80.71)
  silkscreen extent -167,-133 133,133, body extent -133,-126 135,122, height 201
sot23-3 [mil]
  rect 36x50 smd: 1(-38,-43) 2(38,-43) 3(0,43)
  silkscreen extent -55,-5 55,65, body extent -60,-52 60,52, height 44
SOTFL50P160X60-6N [mm]
  rect 0.66x0.31 smd: 1(-0.735,0.5) 2(-0.735,0) 3(-0.735,-0.5) 4(0.735,-0.5) 5(0.735,0) 6(0.735,0.5)
  silkscreen extent -1.7,-0.97 0.6,0.97, body extent -0.8,-0.8 0.8,0.8, height 0.56
TE_284391-8 [mm]
  rect 1.65x1.65 hole 1.1: 1(-12.25,0)
  round 1.65 hole 1.1: 2(-8.75,0) 3(-5.25,0) 4(-1.75,0) 5(1.75,0) 6(5.25,0) 7(8.75,0) 8(12.25,0)
  silkscreen extent -14.78,-4.1 14.15,4.1, body extent -14.38,-4.14 14.12,4.06, height 12.61
TE_640457-2 [mm]
  rect 1.37x1.37 hole 1.02: 1(0,0)
  round 1.37 hole 1.02: 2(2.54,0)
  silkscreen extent -2.02,-0.1 3.81,8.19, body extent -1.3,-0.3 3.78,10.74, height 5.85
VREG_L7805ACD2T [mm]
  rect 3.5x1.6 smd: 1(-6.7,2.54) 3(-6.7,-2.54)
  rect 9.75x12.2 smd paste-7: 4(3.575,0)
  silkscreen extent -6.48,-5 -2.51,5, body extent -7.71,-5.1 7.71,5.1, height 4.61

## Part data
BUZ1: library part Mod-0003, "12 mm, 5 Vdc, 92 dB, Through Hole, Driving Circuit, Magnetic Audio Indicator Buzzer", ADI Part Number=3716-0001, Current=35mA, JLCPCB_PART=NA, LCSC Part Number=N/A, Manufacturer="CUI Devices", Supplier Part Number 1=490-CEM1205IC, Voltage=5V
C1 C4 C5 C6 C7 C8 C9 C10 C11 C12 C14 C15 C18 C19 C26 C28: library part Cap-00005, "Cap Ceramic 0.1uF 50V X7R 10% Pad SMD 0402 125C Automotive T/R", Case Code (Imperial)=0402, Case Code (Metric)=1005, Dielectric Material=Ceramic, LCSC Part Number=C307331, Manufacturer=Murata, Manufacturer Part Number=GRT155R71H104KE01D, Supplier Part Number 1=490-GRT155R71H104KE01DCT-ND, Voltage Rating (DC)=50V
C2 C3 C22 C23 C24 C30 C31: library part Cap-00003, "CAP CER 1UF 10V Y5V 0402", Case Code (Imperial)=0402, Case Code (Metric)=1005, Dielectric Material=Ceramic, LCSC Part Number=C52923, Manufacturer=KEMET, Manufacturer Part Number=C0402C105Z8VAC7867, Max Operating Temperature=85°C, Min Operating Temperature=-30°C, Supplier Part Number 1=399-14873-1-ND, Tolerance=80%, Voltage Rating=10V
C20: library part Cap-00006, "CAP CER 0.47UF 16V Y5V 0402", Capacitance=470nF, Case Code (Imperial)=0402, Case Code (Metric)=1005, Dielectric=Y5V, Dielectric Material=Ceramic, LCSC Part Number=C527993, Manufacturer=Yageo, Manufacturer Part Number=CC0402ZRY5V7BB474, Max Operating Temperature=85°C, Min Operating Temperature=-30°C, Supplier Part Number 1=311-1735-1-ND, Tolerance=80%, Voltage Rating=16V
C25: library part Cap-00001, "CAP CER 4.7UF 16V X5R 0603", Case Code (Imperial)=0603, Case Code (Metric)=1608, Dielectric=X5R, Dielectric Material=Ceramic, LCSC Part Number=C19666, Manufacturer=Samsung, Manufacturer Part Number=CL10A475KO8NNNC, Max Operating Temperature=85°C, Min Operating Temperature=-55°C, Package Quantity=1, Supplier Part Number 1=1276-1784-1-ND, Tolerance=10%, Voltage=16V
C27: library part Cap-00004, "CAP CER 47UF 16V X5R 1210", Case Code (Imperial)=1210, Case Code (Metric)=3225, Dielectric=X5R, Dielectric Material=Ceramic, LCSC Part Number=C77101, Manufacturer=Murata, Manufacturer Part Number=GRM32ER61C476ME15L, Max Operating Temperature=85°C, Min Operating Temperature=-55°C, Package Quantity=1000, Supplier Part Number 1=490-3888-1-ND, Tolerance=20%, Voltage=16V
D1 D4 D5 D6 D7: library part Diode-0009, "DIODE SCHOTTKY 30V 150MA SOT23-3", LCSC Part Number=C47546, Manufacturer="Sangdest Microelectronics", Package Description="3-Pin Small Outline Transistor, Body 2.92 x 1.325 mm, Pitch 0.95 mm", Package Reference=SOT23-3, Package Version="Rev. 12, 03/2016", Peak Reverse Current=2uA, Supplier Part Number 1=1655-BAT54SCT-ND
D9: library part Diode-0002, "DIODE SCHOTTKY 40V 1A SOD323", Average Rectified Current=1A, Case Code (Imperial)=sod123, Color=Blue, Forward Current=25mA, Forward Voltage="600mV @ 1A", LCSC Part Number=C84354, Manufacturer=MCC, Manufacturer Part Number="B5819W TP", Max Operating Temperature=85°C, Max Reverse Voltage (DC)=40V, Min Operating Temperature=-40°C, Package Description="2-Pin Small Outline Diode, Body 2.7 x 1.6 mm, Height 1.35 mm", Package Reference=SOD123, Power Dissipation=110W, Reverse Voltage=5V, Supplier Part Number 1=5819W-TPMSTR-ND, Test Current=20mA
D10: library part Diode-0008, "Rectifier Diode Schottky 40V 2A Automotive 2-Pin SMB T/R", Average Rectified Current=200mA, Capacitance=10pF, Case/Package=SMB, Forward Voltage=800mV, LCSC Part Number=C460673, Manufacturer=Diodes, Max Forward Surge Current (Ifsm)=600mA, Max Operating Temperature=150°C, Max Power Dissipation=200mW, Max Repetitive Reverse Voltage (Vrrm)=30V, Max Reverse Current=2uA, Min Operating Temperature=-65°C, Package Description="2-Pin Small Outline Diode, Body 2.7 x 1.6 mm, Height 1.35 mm", Package Quantity=3000, Package Reference=SOD123, Supplier Part Number 1=B240Q-13-FDICT-ND
DS5 DS12: library part Diode-0005, "LED RED CLEAR 0603 SMD", Case Code (Imperial)=0603, Case Code (Metric)=1608, Color=Red, Forward Current=5mA, Forward Voltage=2.0V, LCSC Part Number=C2286, Lens Color=Colorless, Manufacturer="Vishay Lite-On", Max Operating Temperature=85°C, Min Operating Temperature=-55°C, Operating Temp Range=-40Cto85C, Operating Temperature Classification=Industrial, Package Description="2-Pin Surface Mount Device, Body 3.2 x 1.6 mm", Package Quantity=3000, Package Reference=HSMX-C150, Package Type=ChipLed, Power Dissipation=50mW, Reverse Voltage=5V, Supplier Part Number 1=160-1830-1-ND, Test Current (It)=20mA
DS6: library part Diode-0003, "LED Blue CLEAR 0603 SMD", Case Code (Imperial)=0603, Case Code (Metric)=1608, Color=Blue, Forward (Drive) Current=20mA, Forward Voltage=2.8V, LCSC Part Number=C72041, Lens Color=Colorless, Manufacturer="Vishay Lite-On", Max Operating Temperature=80°C, Min Operating Temperature=-20°C, Package Description="2-Pin Surface Mount Device, Body 1.6 x 0.8 mm", Package Quantity=1, Power Dissipation=76mW, Reverse Voltage=5V, Supplier Part Number 1=160-1827-1-ND, Test Current=5mA
DS8: library part Diode-0006, "LED Yellow CLEAR 0603 SMD", Case Code (Imperial)=0603, Case Code (Metric)=1608, Color=Yellow, Forward Current=30mA, Forward Voltage=2.0V, LCSC Part Number=C72038, Lens Color=Colorless, Manufacturer="Vishay Lite-On", Max Operating Temperature=85°C, Min Operating Temperature=-55°C, Package Quantity=1, Power Dissipation=75mW, Resistance="390 Ohm", Reverse Voltage=5V, Supplier Part Number 1=160-1831-1-ND, Test Current=5mA, Voltage Rating="50 V"
DS9: library part Diode-0004, "LED Orange CLEAR 0603 SMD", Case Code (Imperial)=0603, Case Code (Metric)=1608, Color=Orange, Forward (Drive) Current=20mA, Forward Current=5mA, Forward Voltage=2.0V, LCSC Part Number=C434425, Lens Color=Colorless, Manufacturer="Vishay Lite-On", Max Operating Temperature=85°C, Min Operating Temperature=-55°C, Package Description="2-Pin Surface Mount Device, Body 1.6 x 0.8 mm", Supplier Part Number 1=160-1829-1-ND
DS11: library part Diode-0007, "LED Green CLEAR 0603 SMD", Average Rectified Current=2A, Case Code (Imperial)=0603, Case Code (Metric)=1608, Case\Package=SOIC, Clock Frequency="100 KHz", Color=Green, Forward Current=5mA, Forward Voltage=2.0V, Frequency="400 KHz", LCSC Part Number=C72043, Lens Color=Colorless, Manufacturer="Vishay Lite-On", Max Operating Temperature=80°C, Max Repetitive Reverse Voltage (Vrrm)=40V, Max Reverse Current=500uA, Max Supply Voltage="5.5 V", Min Operating Temperature=-20°C, Min Supply Voltage="1.7 V", Nominal Supply Current="2 mA", Package Quantity=3000, Peak Non-Repetitive Surge Current=50A, Power Dissipation=76mW, Reverse Voltage=5V, Supplier Part Number 1=160-1832-1-ND
F1 F2: library part MF-MSMF050-2, "15VDC 500mA", Case Code (Imperial)=1812, Case Code (Metric)=4532, Current Rating=100A, LCSC Part Number=C17313, Manufacturer=Bourns, Max Operating Temperature=85°C, Min Operating Temperature=-40°C, Operating Supply Voltage=15V, Package Description="2-Pin Surface Mount Device, Body 4.55 x 3.24 mm", Package Quantity=2000, Power Dissipation=800mW, Resistance=150mR, Supplier Part Number 1=MF-MSMF050-2CT-ND, Trip Current=1A
F3: library part FEMTOASMDC005F-2, "Ptc Reset Fuse 15V 50MA 0603", Case Code (Imperial)=0603, Case Code (Metric)=1608, LCSC Part Number=C2832197, Manufacturer=Littelfuse, Max Current Rating=10A, Package Description="2-Pin Surface Mount Device, Body 4.55 x 3.24 mm", Package Reference=MF-MSMF050-2, Supplier Part Number 1=F9952CT-ND, Trip Current=150mA
J1 J6: library part CON-0011, "Conn Terminal Block F 8 POS 3.5mm Solder ST T", Color=Green, LCSC Part Number=N/A, Manufacturer="TE Connectivity", Package=None, Supplier Part Number 1=571-284391-8
J4: library part CON-0003, "CONN HEADER 6 POS 2.54", Color=Black, LCSC Part Number=C2833331, Manufacturer="Wurth Electronics", Max Operating Temperature=125°C, Min Operating Temperature=-40°C, Supplier Part Number 1=732-5319-ND
J5: library part CON-0010, "3000 Series; 2.54mm Pitch 26 Way 2 Row Right", Color=Black, Current=12A, Current Rating=1A, Flammability Rating="UL94 V-0", LCSC Part Number=N/A, Manufacturer=3M, Max Current Rating=2A, Max Operating Temperature=105°C, Max Supply Voltage (AC)=300V, Min Operating Temperature=-55°C, Package Quantity=250, Supplier Part Number 1=MHR26S-ND
J8: library part CON-0013, "Header, Polarized; MTA-100; 2; 250 VAC; Polye", Color=Natural,White,Beige, Housing Color=Natural, LCSC Part Number=C86501, Manufacturer="TE Connectivity", Supplier Part Number 1=A19423-ND
J9: library part CON-0014, "MTA-100 HEADER  Friction Lock R/A 2POS 2.54MM", LCSC Part Number=C86507, Manufacturer="AMP - TE CONNECTIVITY", Supplier Part Number 1=A1926-ND
J10: library part CON-0006, "Pluggable Term Blocks BCH-508HS- 2 GN 5.08", Current=13.5A, Flammability Rating="UL94 V-0", Housing Color=Green, LCSC Part Number=N/A, Manufacturer="Phoenix Contact", Manufacturer Part Number=5442002, Package Quantity=50, Supplier Part Number 1=277-11311-ND, Voltage=300V, Voltage Rating=200V
J11: library part CON-0005, "Pluggable Term Blocks BCH-508HS- 2 GR 5.08", Color=Grey, Current Rating=12A, LCSC Part Number=N/A, Manufacturer="Phoenix Contact", Manufacturer Part Number=5433668, Package Quantity=100, Supplier Part Number 1=277-11218-ND, Voltage Rating=320V
J12: library part CON-0001, "Conn Header Right angle 3.5 pitch 2P", Color=Black, LCSC Part Number=C409115, Manufacturer="Adam Equipment", Package Quantity=1, Supplier Part Number 1=2057-EBSA-02-A-ND
MTG1 MTG2 MTG3 MTG4: library part Hole-001, "Plated"
Q1 Q2 Q3 Q5 Q7 Q9 Q10 Q13 Q14: library part Tran-0002, "Trans GP BJT NPN 60V 0.2A 350mW Automotive 3-Pin SOT-23 T/R", Case/Package=SOT-23-3, Collector-emitter Voltage-Max=400mV, Frequency=250MHz, LCSC Part Number=C20526, Manufacturer="ON Semiconductor / Fairchild", Max Collector Current=200mA, Max Operating Temperature=150°C, Min Operating Temperature=-55°C, Package Description="3-Pin Small Outline Transistor, Body 2.9 x 1.3 mm, Pitch 0.95 mm", Package Reference="SOT-23 (318-08)", Power=225mW, Supplier Part Number 1=58K9431
Q4 Q8: library part Tran-0001, "Mosfet P-channel 30V 4A SOT23-3", Case/Package=SOT-23-3, Collector Base Voltage (VCBO)=60V, Collector Emitter Breakdown Voltage=40V, Collector Emitter Saturation Voltage=300mV, Continuous Drain Current=4A, Current Rating=200mA, Drain to Source Voltage (Vdss)=30V, Emitter Base Voltage (VEBO)=6V, Frequency=300MHz, Frequency (Max)=NotRequiredMHz, Gate-Source Voltage (Max)=?12V, Input Capacitance=645pF, LCSC Part Number=C15127, Manufacturer="Alpha & Omega Semiconductor", Manufacturer Part Number=AO3401AL, Max Operating Temperature=150°C, Max Power Dissipation=1.4W, Min Operating Temperature=-55°C, Operating Temp Range=-55Cto150C, Operating Temperature Classification=Military, Output Power (Max)=NotRequiredW, Package Description="3-Pin Small Outline Transistor, Body 2.95 x 1.6 mm, Pitch 0.95 mm", Package Quantity=1, Package Reference=SOT-23-3L, Package Type=SOT-23, Power Dissipation=350mW, Power Gain=NotRequireddB, Supplier Part Number 1=AO3401AL-ND
R1: library part Res-00013, "Res Thick Film 0402 120 Ohm 1% 0.063W(1/16W) ±100ppm/C Pad SMD Automotive T/R", Case Code (Imperial)=0402, Case Code (Metric)=1005, LCSC Part Number=C25079, Manufacturer="Stackpole Electronics", Manufacturer Part Number=RMCF0402FT120R, Max Operating Temperature=155°C, Max Power Dissipation=63mW, Min Operating Temperature=-55°C, Package Quantity=10000, Resistor Type="Thick Film", Supplier Part Number 1=RMCF0402FT120RCT-ND, Temperature Coefficient=100ppm/°C, Tolerance=1%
